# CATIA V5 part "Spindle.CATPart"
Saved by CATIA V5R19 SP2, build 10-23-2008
Part number: Spindle
Revision: ANY
Definition: UNKNOWN
Nomenclature: Spindle
Source: Unknown
Bounding box of the stored display mesh (mm): x 0 to 39, y -11 to 11, z -11 to 11
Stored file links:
  Z:\fausse table rondelle-20220905T211342Z-001\fausse table rondelle\Spindle.CATPart
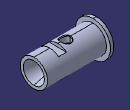
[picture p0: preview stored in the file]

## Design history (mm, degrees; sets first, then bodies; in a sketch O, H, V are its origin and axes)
AxisSystem1: origin (0, 0, 0), X (1, 0, 0), Y (0, 1, 0), Z (0, 0, 1)
Body1 "Schnitt-Rotation1" (main body)
  Solid1: solid without history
